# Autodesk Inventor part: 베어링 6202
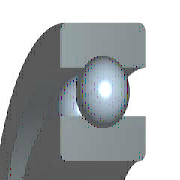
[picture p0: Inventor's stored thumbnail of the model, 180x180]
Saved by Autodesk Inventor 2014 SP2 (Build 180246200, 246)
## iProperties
Created: 2015-12
Part Number: 베어링 6202
Material: 강철, 연강
Description: 깊은 그루브 볼 베어링
Document SubType Name: Modeling
Standard: KS B 2023
Designer: mdu
Standards Organization: KS
Language: ko-KR
Size Designation: 6202 - 15 x 35 x 11
Categories: <MemberInstance><Categories><Category DisplayName="샤프트 부품" InternalName="7f7aeb1f-a693-4053-b835-cee3144e0d98" Mnemonic="SHFT"><Category DisplayName="베어링" Inter
Density: 7.86 g/cm^3
Mass: 45.8724 g
Surface Area: 51.5584 cm^2
Volume: 5.83618 cm^3
Appearance: 노란색
Company: 한국ATC센터
IsCustomPart: 1
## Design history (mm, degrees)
sketch "스케치" dims "d0" = 5.2 (= -0.26 x WD + 0.26 x BD)
  geometry: L1 (2.9, 12.5)-(8.1, 12.5); L2 (5.5, 12.5)-(5.5, 9.9); L3 (5.5, 12.5)-(5.5, 15.1); L4 (3.568, 10.76)-(0, 10.76); L5 (0, 7.5)-(11, 7.5); L6 (3.568, 14.24)-(0, 14.24); L7 (0, 17.5)-(11, 17.5); L8 (11, 7.5)-(11, 10.76); L9 (7.432, 10.76)-(11, 10.76); L10 (7.432, 14.24)-(11, 14.24); L11 (11, 17.5)-(11, 14.24); L12 (-1.4, 0)-(8.4, 0) reference; L13 (0, -0.3)-(0, 5.3) reference
  constraints: 22 end point, 4 point on line, 2 collinear, 2 perpendicular, 2 symmetric about line, 1 midpoint, 1 parallel, 14 other
  dimensions: "d9" = 15 diameter of L5 L12 (= WD); "d11" = 35 diameter of L7 L12 (= BD); "d12" = 11 distance between parallel lines of L8 L13 (= KB); "d13" = 21.52 diameter of L9 L12 (= 0.326 x BD + 0.674 x WD)
revolve "본체" stored, may be unused: angle "d6" = 90 deg
revolve "볼" stored, may be unused: angle "d7" = 90 deg
pattern_circular "IDS_ARRAYBALL[SIMPL:T]" dims angle "d3" = 360 deg
body "Solid1"
fillet "모깎기1" dims "d1" = 0.6 (= KRS)
other parameters: "WD" = 15 [user parameter; used in 5 equation terms], "BD" = 35 [user parameter; used in 5 equation terms], "KB" = 11 [user parameter; used in 1 equation term], "KRS" = 0.6 [user parameter; used in 1 equation term], "d4" = 0, "d5" = 0, "d8" = 0, "d14" = 0, "d15" = 0, "BBA" = 0 [user parameter], "BC0" = 3750000 [user parameter], "BC" = 7800000 [user parameter], "BR" = 17.5 (= 0.5 x BD) [user parameter], "WR" = 7.5 (= 0.5 x WD) [user parameter]
